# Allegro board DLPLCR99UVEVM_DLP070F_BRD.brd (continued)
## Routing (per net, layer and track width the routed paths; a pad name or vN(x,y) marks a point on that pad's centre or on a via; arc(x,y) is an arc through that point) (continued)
VDD_DMD: length 187.1
  TOP w0.381: C52.2 v1(107.32,20.75) ; C134.2 v1(47.4,51.69) ; R58.2 91.33,84.91 v1(92.19,84.05) ; C103.2 v1(64.25,61.73) ; C45.2 v1(102.87,15.04) ; C49.2 48.92,3.58 v1(49.65,3.58) ; C147.2 v1(96.18,9.43) ; C150.2 v1(46.13,26.29) ; C73.2 84.93,3.99 v1(84.7,3.76) ; U22.5 v1(111.3,22.06) ; C64.2 v1(43.59,26.92) ; C57.2 v1(104.14,16.94) ; v1(105.51,15.05) 105.79,15.33 U23.5 ; C66.2 v1(104.14,39.8) ; C102.2 v1(62.35,61.73) ; C81.2 55.27,4.85 v1(56,4.85) ; C93.2 50.14,6.89 v1(50.28,6.76) ; C146.2 v1(43.59,32.64) ; C130.2 v1(104.14,41.71) ; C78.2 v1(43.59,36.45) ; C84.2 v1(85.21,61.73) ; C56.2 v1(78.22,68.08) ; C60.2 v1(86.66,4.35) ; C154.2 51.46,6.12 v1(52.19,6.12) ; C95.2 53.37,5.49 v1(54.09,5.49) ; C100.2 v1(43.59,30.73) ; C109.2 v1(68.06,61.73) ; C112.2 v1(76.32,64.91) ; C54.2 v1(107.95,48.06) ; C166.2 v1(83.3,61.73) ; v1(82.57,83.51) 82.57,84.61 82.3,84.87 R61.2 81.44,84.87 81.17,84.6 v1(81.17,83.51) ; C126.2 v1(53.12,57.4) ; C196.2 v1(93.23,86.38) ; C61.2 v1(88.56,4.35) ; C156.2 96.66,6.51 v1(96.66,7.24) ; C53.2 v1(102.24,8.69) ; C105.2 v1(47.4,11.05) ; C79.2 v1(43.59,34.54) ; C51.2 v1(94.28,3.72) ; v1(42.79,9.02) 43.22,9.45 C72.2 ; C153.2 v1(58.54,61.73) ; C80.2 v1(43.59,38.35) ; C151.2 v1(100.33,11.23) ; C99.2 v1(46.13,14.86) ; C157.2 v1(46.13,16.76) ; C62.2 v1(94.28,7.53) ; C104.2 v1(48.67,9.14) ; C132.2 v1(46.13,49.78) ; C131.2 v1(41.05,44.07) ; C145.2 106.68,37.9 ; C55.2 v1(101.08,63.64) ; C83.2 v1(102.87,55.04) ; v1(54.88,57.58) 54.88,58.3 C127.2 ; v1(56.15,59.49) 56.29,59.63 C111.2 ; C85.2 v1(46.13,20.57) ; C164.2 v1(46.77,12.95) ; C110.2 v1(66.16,61.73) ; C152.2 v1(107.32,40.44) ; C40.2 v1(98.54,61.1) ; C101.2 v1(43.59,28.83) ; C47.2 v1(56.63,64.27) ; C67.2 v1(92.37,5.62) ; C107.2 v1(60.44,61.73) ; C129.2 v1(90.47,4.99) ; C133.2 v1(43.59,40.26) ; C43.2 v1(104.14,24.56) ; C171.2 v1(100.97,13.13) ; C167.2 v1(90.92,61.73) ; C48.2 v1(46.13,47.88) ; C42.2 v1(103.27,18.95) ; C65.2 v1(98.09,10.7) ; C59.2 v1(82.85,4.35) ; C200.2 v1(108.59,43.55) ; C50.2 v1(40.42,22.48)
  TOP w0.508: v1(109.21,25.4) 108.96,25.14 C74.2 ; C69.2 v1(65.65,64.64) ; C75.2 108.32,45.54 v1(108.58,45.29) ; v1(39.13,34.75) 39.41,34.47 C71.2 ; C91.1 v1(91.02,69.8) ; C91.1 93.87,68.22 94.25,67.84 v1(96.16,67.84) ; C91.1 93.87,70.26 94.5,70.89 v1(96.16,70.89) ; v1(83.96,66.12) 84.17,65.91 C76.2 ; C92.1 60.21,70.76 60.6,71.14 v1(62.5,71.14) ; C92.1 58.61,69.8 v1(57.8,69) ; C92.1 60.21,68.1 60.47,67.84 v1(62.5,67.84) ; v1(38.96,45.19) 39.16,45.39 C70.2
  BOTTOM w0.381: TP15.1 98.16,86.54 ; TP15.1 98.16,88.76 ; TP15.1 95.93,86.54 ; TP15.1 95.93,88.76
  BOTTOM w0.508: U16.AF18 v1(78.86,45.98) ; U16.T4 v1(58.54,33.28) ; U16.AF10 v1(66.16,45.98) ; U16.AF6 v1(61.08,45.98) ; U16.D20 v1(81.4,18.04) ; U16.D24 v1(86.48,18.04) ; U16.AJ1 v1(54.73,49.79) ; U16.H16 v1(73.78,23.12) ; U16.H28 v1(91.56,23.12) ; U16.F10 v1(66.16,20.58) ; U16.AE13 v1(69.97,44.71) ; U16.AF28 v1(91.56,45.98) ; U16.Y28 v1(91.56,38.36) ; U16.A3 v1(57.27,14.23) ; U16.AD12 v1(68.7,43.44) ; U16.H24 v1(86.48,23.12) ; U16.AH18 v1(78.86,48.52) ; U16.V28 v1(91.56,35.82) ; U16.D8 v1(63.62,18.04) ; U16.AF26 v1(89.02,45.98) ; U16.F8 v1(63.62,20.58) ; U16.AJ29 v1(92.83,49.79) ; U16.B4 v1(58.54,15.5) ; U16.AH14 v1(71.24,48.52) ; U16.C21 v1(82.67,16.77) ; U16.C29 v1(92.83,16.77) ; U16.AL29 v1(92.83,52.33) ; U16.N29 v1(92.83,29.47) ; U16.C1 v1(54.73,16.77) ; U16.AF12 v1(68.7,45.98) ; U16.AH12 v1(68.7,48.52) ; U16.H22 v1(83.94,23.12) ; U16.F16 v1(73.78,20.58) ; U16.T28 v1(91.56,33.28) ; U16.AA29 v1(92.83,39.63) ; U16.F18 v1(78.86,20.58) ; U16.A29 v1(92.83,14.23) ; U16.AJ21 v1(82.67,49.79) ; U16.AH10 v1(66.16,48.52) ; U16.AD28 v1(91.56,43.44) ; U16.AJ5 v1(59.81,49.79) ; U16.AF24 v1(86.48,45.98) ; U16.H20 v1(81.4,23.12) ; U16.H18 v1(78.86,23.12) ; U16.AD10 v1(66.16,43.44) ; U16.AJ31 v1(95.37,49.79) ; U16.AH16 v1(73.78,48.52) ; U16.AB4 v1(58.54,40.9) ; U16.AE15 v1(72.51,44.71) ; U16.P28 v1(91.56,30.74) ; U16.AK2 v1(56,51.06) ; U16.AF22 v1(83.94,45.98) ; U16.AJ11 v1(67.43,49.79) ; U16.F20 v1(81.4,20.58) ; U16.L3 v1(57.27,26.93) ; U16.V4 v1(58.54,35.82) ; U16.F12 v1(68.7,20.58) ; U16.D18 v1(78.86,18.04) ; U16.D16 v1(73.78,18.04) ; U16.C13 v1(69.97,16.77) ; U16.AD8 v1(63.62,43.44) ; U16.P4 v1(58.54,30.74) ; U16.D12 v1(68.7,18.04) ; U16.K4 v1(58.54,25.66) ; U16.C31 v1(95.37,16.77) ; U16.M4 v1(58.54,28.2)
VDDA_DMD: length 52.8
  TOP w0.381: 70.03,85.91 TP16.1 ; TP16.1 72.25,88.13 ; TP16.1 72.25,85.91 ; TP16.1 70.03,88.13 ; C98.2 v1(106.68,26.53) ; C148.2 v1(104.14,22.64) ; C97.2 v1(106.68,28.41)
  LY2-SIG w0.381: 70.03,85.91 TP16.1 ; TP16.1 70.03,88.13 ; TP16.1 72.25,88.13 ; TP16.1 72.25,85.91
  BOTTOM w0.381: v1(112.69,25.7) 110.89,27.51 C124.2 ; C115.2 v1(108.35,52.96) ; C113.2 v1(91.56,67.84) ; v1(73.3,70.08) 75.12,70.08 C123.2
  BOTTOM w0.508: U16.H26 v1(89.02,23.12) ; U16.D14 v1(71.24,18.04) ; U16.AE27 v1(90.29,44.71) ; U16.AH24 v1(86.48,48.52) ; U16.G11 v1(67.43,21.85) ; U16.K28 v1(91.56,25.66) ; U16.AD22 v1(83.94,43.44) ; U16.AB28 v1(91.56,40.9) ; U16.G15 v1(72.51,21.85) ; U16.AF20 v1(81.4,45.98) ; U16.AH20 v1(81.4,48.52) ; U16.AD18 v1(78.86,43.44) ; U16.H10 v1(66.16,23.12) ; U16.D10 v1(66.16,18.04) ; U16.F6 v1(61.08,20.58) ; U16.H12 v1(68.7,23.12) ; U16.AE19 v1(80.13,44.71) ; U16.H8 v1(63.62,23.12) ; U16.H14 v1(71.24,23.12) ; U16.AD16 v1(73.78,43.44) ; U16.AD24 v1(86.48,43.44) ; U16.AD14 v1(71.24,43.44)
  vias: v1(70.81,84.56) v1(71.92,85.01)
AMUX_OUT: length 79.8
  TOP w0.203: J8.1 v1(142.76,18.19)
  LY2-SIG w0.145: v1(77.59,19.31) 76.72,18.44 76.72,16.41 81.04,12.09 97.04,12.09 98.95,13.99 103.9,13.99 105.17,12.72 114.7,12.72 116.73,14.76 141.11,14.76 142.76,16.41 v1(142.76,18.19)
  BOTTOM w0.508: U16.E17 v1(77.59,19.31)
DCLK_AN: length 146
  TOP w0.127: v1(74.06,109.73) 74.44,110.11 74.44,110.63 74.11,110.97 74.11,112.77 73.48,113.4 73.48,115.2 73.36,115.32 J1.34
  LY4-SIG w0.127: v1(74.06,109.73) 74.31,109.48 74.31,108.23 78.1,104.44 78.1,78.21 77.43,77.55 74.97,77.55 74.18,78.33 74.18,92.79 72.2,94.77 68.85,94.77 67.07,92.99 67.07,73.49 62.78,69.19 59.08,69.19 47.51,57.63 47.51,52.98 49.8,50.7 49.8,42.52 53.26,39.06 53.26,32.18 54.73,30.7 v1(54.73,29.47)
  BOTTOM w0.508: U16.N1 v1(54.73,29.47)
DCLK_AP: length 145.6
  TOP w0.127: v1(74.98,109.73) 74.7,110.01 74.7,110.74 74.36,111.07 74.36,112.88 73.74,113.5 73.74,115.2 73.86,115.32 J1.33
  LY4-SIG w0.127: v1(74.98,109.73) 74.62,109.37 74.62,108.36 78.41,104.57 78.41,78.08 77.56,77.24 74.84,77.24 73.88,78.2 73.88,92.66 72.08,94.46 68.98,94.46 67.38,92.86 67.38,73.36 62.91,68.88 59.21,68.88 47.82,57.5 47.82,53.11 50.11,50.83 50.11,42.65 53.57,39.19 53.57,32.31 55.14,30.74 v1(56,30.74)
  BOTTOM w0.508: U16.P2 v1(56,30.74)
DCLK_BN: length 152.1
  TOP w0.127: J2.34 117.18,115.32 117.3,115.2 117.3,113.4 117.87,112.82 117.87,110.85 v1(117.54,110.51)
  LY4-SIG w0.127: v1(117.54,110.51) 117.85,110.21 117.85,108.94 121.45,105.33 121.45,96.27 119.95,94.77 119.95,93.67 121.42,92.2 121.42,41.93 121.13,41.63 120.07,41.63 119.78,41.93 119.78,45.77 119.16,46.38 118.11,46.38 117.57,45.85 117.57,35.61 105.99,24.03 104,24.03 101.25,21.27 101.25,18.73 92.78,10.26 83.21,10.26 81.1,12.37 81.1,14.88 80.59,15.39 80.1,15.39 79.8,15.09 79.28,15.09 v1(78.86,15.5)
  BOTTOM w0.508: U16.B18 v1(78.86,15.5)
DCLK_BP: length 151.8
  TOP w0.127: J2.33 117.68,115.17 117.55,115.05 117.55,113.5 118.13,112.93 118.13,110.85 v1(118.46,110.51)
  LY4-SIG w0.127: v1(80.13,14.23) 80.13,14.98 80.23,15.08 80.46,15.08 80.79,14.76 80.79,12.24 83.08,9.95 92.91,9.95 101.56,18.61 101.56,21.15 104.13,23.72 106.11,23.72 117.88,35.48 117.88,45.72 118.24,46.07 119.03,46.07 119.47,45.64 119.47,41.8 119.94,41.32 121.26,41.32 121.73,41.8 121.73,92.33 120.26,93.8 120.26,94.64 121.76,96.14 121.76,105.46 118.15,109.06 118.15,110.21 v1(118.46,110.51)
  BOTTOM w0.508: U16.A19 v1(80.13,14.23)
DCLK_CN: length 144.4
  LY6-SIG w0.107: v1(67.43,52.33) 68.18,53.07 68.36,53.07 68.86,52.56 68.86,52.37 68.18,51.69 67.1,51.69 63.55,55.24 63.55,92.18 63.84,92.48 64.49,92.48 64.79,92.18 64.79,61.31 65.36,60.73 66.54,60.73 67.07,61.26 67.07,94.12 72.79,99.84 72.79,103.24 78.78,109.24 80.05,109.24 80.53,109.72 80.53,111.4 v1(80.82,111.68)
  BOTTOM w0.127: v1(80.82,111.68) 80.48,112.02 80.48,113.49 81.24,114.24 81.24,115.2 81.36,115.32 J3.34
  BOTTOM w0.508: U16.AL11 v1(67.43,52.33)
DCLK_CP: length 144
  LY6-SIG w0.107: v1(69.97,52.33) 69.26,52.33 68.31,51.38 66.97,51.38 63.24,55.11 63.24,92.31 63.71,92.79 64.62,92.79 65.1,92.31 65.1,61.44 65.49,61.04 66.41,61.04 66.76,61.39 66.76,94.25 72.48,99.97 72.48,103.37 78.66,109.55 79.93,109.55 80.23,109.85 80.23,111.35 v1(79.9,111.68)
  BOTTOM w0.127: J3.33 80.86,115.32 80.98,115.2 80.98,114.34 80.23,113.59 80.23,112.02 v1(79.9,111.68)
  BOTTOM w0.508: U16.AL13 v1(69.97,52.33)
DCLK_DN: length 145.7
  LY6-SIG w0.107: v1(94.1,48.52) 94.55,48.52 94.89,48.18 94.89,47.85 94.59,47.56 94.02,47.56 93.39,48.18 93.39,48.82 94.89,50.31 105.63,50.31 107.45,52.14 109.57,52.14 121.61,64.18 121.61,79.65 122.07,80.11 122.75,80.11 122.95,79.91 122.95,67.64 123.51,67.08 124.68,67.08 125.22,67.62 125.22,104.9 125.57,105.25 126.2,105.25 126.43,105.02 126.43,95.63 126.89,95.17 127.43,95.17 127.99,95.73 127.99,106.25 127.43,106.81 125.21,106.81 124.51,107.51 124.51,111.08 124.33,111.26 124.33,111.38 v1(124.63,111.68)
  BOTTOM w0.127: J4.34 125.17,115.32 125.05,115.2 125.05,114.24 124.3,113.49 124.3,112.02 v1(124.63,111.68)
  BOTTOM w0.508: U16.AH30 v1(94.1,48.52)
DCLK_DP: length 145.3
  LY6-SIG w0.107: v1(123.71,111.68) 124.02,111.38 124.02,111.13 124.2,110.95 124.2,107.38 125.09,106.5 127.3,106.5 127.68,106.12 127.68,95.86 127.3,95.48 127.02,95.48 126.74,95.76 126.74,105.15 126.33,105.56 125.45,105.56 124.91,105.02 124.91,67.74 124.55,67.39 123.64,67.39 123.26,67.77 123.26,80.03 122.88,80.42 121.94,80.42 121.3,79.78 121.3,64.31 109.44,52.45 107.33,52.45 105.5,50.62 94.76,50.62 93.08,48.94 93.08,48.06 93.89,47.25 v1(95.37,47.25)
  BOTTOM w0.127: v1(123.71,111.68) 124.05,112.02 124.05,113.59 124.8,114.34 124.8,115.2 124.67,115.32 J4.33
  BOTTOM w0.508: U16.AG31 v1(95.37,47.25)
DD_A0N: length 153.3
  TOP w0.127: v1(81.11,113.33) 81.48,113.7 81.48,115.2 81.36,115.32 J1.18
  LY4-SIG w0.127: v1(81.11,113.33) 81.37,113.59 81.37,114.81 77.43,118.74 58.46,118.74 36.01,96.3 36.01,30.81 43.75,23.07 44.39,23.07 45.74,21.72 49.38,21.72 51.47,19.62 54.21,19.62 54.45,19.86 54.98,19.86 55.21,19.63 55.69,19.63 56,19.94 v1(56,20.58)
  BOTTOM w0.508: U16.F2 v1(56,20.58)
DD_A0P: length 152.6
  TOP w0.127: v1(82.03,113.33) 81.74,113.63 81.74,115.2 81.86,115.32 J1.17
  LY4-SIG w0.127: v1(82.03,113.33) 81.68,113.69 81.68,114.93 77.56,119.05 58.33,119.05 35.7,96.42 35.7,30.68 43.63,22.76 44.26,22.76 45.61,21.41 49.25,21.41 51.34,19.31 v1(54.73,19.31)
  BOTTOM w0.508: U16.E1 v1(54.73,19.31)
DD_A1N: length 148.9
  TOP w0.127: J1.22 79.36,115.32 79.48,115.2 79.48,114.23 80.13,113.58 80.13,113.06 79.14,112.07 79.14,110.92 v1(78.81,110.59)
  LY4-SIG w0.127: v1(78.81,110.59) 79.09,110.87 79.09,112.12 80.07,113.11 80.07,113.64 79.49,114.22 79.49,114.39 78.55,115.34 68.29,115.34 64.91,111.96 62.17,111.96 52.34,102.13 52.34,100.02 40.63,88.31 40.63,45.53 39.49,44.4 39.49,41.04 40.63,39.9 40.63,27.76 43.18,25.21 44.86,25.21 46.58,23.49 50.09,23.49 52.3,21.28 55.06,21.28 55.41,21.64 55.41,22.48 55.03,22.87 55.03,23.55 54.75,23.82 53.94,23.82 53.72,23.61 53.72,22.86 v1(54.73,21.85)
  BOTTOM w0.508: U16.G1 v1(54.73,21.85)
DD_A1P: length 148.4
  TOP w0.127: v1(79.72,110.59) 79.39,110.92 79.39,111.96 80.38,112.95 80.38,113.69 79.74,114.34 79.74,115.2 79.86,115.32 J1.21
  LY4-SIG w0.127: v1(79.72,110.59) 79.4,110.92 79.4,111.99 80.38,112.98 80.38,113.77 79.8,114.34 79.8,114.52 78.68,115.65 68.16,115.65 64.79,112.27 62.04,112.27 52.03,102.26 52.03,100.15 40.32,88.44 40.32,45.66 39.18,44.53 39.18,40.91 40.32,39.77 40.32,27.63 43.05,24.9 44.73,24.9 46.45,23.18 49.96,23.18 52.17,20.97 55.19,20.97 55.72,21.51 55.72,22.61 55.34,23 55.34,23.79 v1(54.73,24.39)
  BOTTOM w0.508: U16.J1 v1(54.73,24.39)
DD_A2N: length 154
  TOP w0.127: J1.26 77.36,115.32 77.48,115.2 77.48,113.26 78.15,112.59 78.15,112.04 77.28,111.18 77.28,110.66 v1(76.95,110.33)
  LY4-SIG w0.127: v1(76.95,110.33) 77.33,109.95 77.33,107.21 80.69,103.85 80.69,86.79 90.9,76.58 90.9,72.85 88.59,70.54 74.7,70.54 73.29,69.13 73.29,63.6 68.34,58.65 58.41,58.65 51.6,51.84 51.6,43.2 53.42,41.38 54.11,41.38 57.85,37.64 57.85,36.6 57.34,36.09 57.34,35.35 57.87,34.82 57.87,34.24 57.47,33.84 57.47,32.78 58,32.26 58,31.65 57.44,31.09 57.44,30.43 57.9,29.97 57.9,29.13 57.4,28.63 57.4,27.81 57.95,27.25 57.95,26.7 57.4,26.14 57.4,25.34 57.92,24.81 57.92,24.13 57.57,23.78 57.57,22.6 64.28,15.9 64.28,14.88 62.88,13.49 62.05,13.49 60.99,14.54 60.46,14.54 60.27,14.73 60.27,15.26 60.5,15.5 v1(61.08,15.5)
  BOTTOM w0.508: U16.B6 v1(61.08,15.5)
DD_A2P: length 153.4
  TOP w0.127: J1.25 77.86,115.32 77.74,115.2 77.74,113.36 78.4,112.7 78.4,111.94 77.54,111.07 77.54,110.66 v1(77.87,110.33)
  LY4-SIG w0.127: v1(77.87,110.33) 77.64,110.1 77.64,107.34 81,103.98 81,86.92 91.21,76.71 91.21,72.72 88.71,70.23 74.83,70.23 73.6,69 73.6,63.47 68.47,58.34 58.54,58.34 51.91,51.71 51.91,43.32 53.55,41.69 54.24,41.69 58.16,37.77 58.16,36.47 57.65,35.97 57.65,35.48 58.18,34.95 58.18,34.11 57.78,33.71 57.78,32.91 58.31,32.38 58.31,31.52 57.75,30.96 57.75,30.56 58.21,30.1 58.21,29.01 57.71,28.5 57.71,27.93 58.26,27.38 58.26,26.57 57.71,26.01 57.71,25.47 58.23,24.94 58.23,24 57.88,23.65 57.88,22.73 64.59,16.03 64.59,14.75 63.01,13.18 61.92,13.18 60.87,14.23 v1(59.81,14.23)
  BOTTOM w0.508: U16.A5 v1(59.81,14.23)
DD_A3N: length 151.9
  TOP w0.127: v1(75.38,111.25) 75.71,111.58 75.71,112.6 76.17,113.06 76.17,113.69 75.48,114.37 75.48,115.2 75.36,115.32 J1.30
  LY4-SIG w0.127: v1(54.73,26.93) 54.73,26.43 54.91,26.26 55.24,26.26 55.69,26.72 55.69,26.97 54.96,27.71 48.89,27.71 45.71,30.88 45.71,35.66 47.89,37.85 47.89,41.35 44.08,45.16 44.08,58.67 49.32,63.91 49.32,72.5 55.36,78.54 55.36,88.24 56.68,89.56 58.21,89.56 59.05,88.72 59.05,73.74 59.53,73.26 60.98,73.26 61.48,73.77 61.48,93.12 73.21,104.84 73.21,110.15 73.7,110.64 75.49,110.64 75.68,110.83 75.68,110.95 v1(75.38,111.25)
  BOTTOM w0.508: U16.L1 v1(54.73,26.93)
DD_A3P: length 151.3
  TOP w0.127: J1.29 75.86,115.32 75.74,115.2 75.74,114.47 76.42,113.79 76.42,112.95 75.96,112.5 75.96,111.58 v1(76.3,111.25)
  LY4-SIG w0.127: v1(56,25.66) 56,27.09 55.08,28.02 49.01,28.02 46.02,31.01 46.02,35.53 48.2,37.72 48.2,41.48 44.39,45.29 44.39,58.54 49.63,63.78 49.63,72.37 55.67,78.41 55.67,88.11 56.81,89.25 58.08,89.25 58.74,88.59 58.74,73.61 59.4,72.95 61.11,72.95 61.79,73.64 61.79,92.99 73.52,104.72 73.52,110.03 73.83,110.33 75.62,110.33 75.99,110.7 75.99,110.95 v1(76.3,111.25)
  BOTTOM w0.508: U16.K2 v1(56,25.66)
DD_A4N: length 155
  TOP w0.127: J1.38 71.36,115.32 71.48,115.2 71.48,114.24 70.58,113.34 70.58,112.62 70.93,112.26 70.93,111 v1(70.62,110.69)
  LY4-SIG w0.127: v1(62.35,14.23) 62.78,14.65 62.78,14.85 56.45,21.18 56.45,22.5 56.55,22.61 56.55,23.64 55.21,24.99 49.09,24.99 44.09,29.99 44.09,30.94 43.8,31.23 42.82,31.23 41.83,32.22 41.83,63.04 47.06,68.27 47.06,90.42 47.85,91.21 49.22,91.21 49.9,90.52 49.9,80.12 50.88,79.15 52.33,79.15 53.46,80.27 53.46,89.1 70.91,106.55 70.91,110.41 v1(70.62,110.69)
  BOTTOM w0.508: U16.A7 v1(62.35,14.23)
DD_A4P: length 154.4
  TOP w0.127: J1.37 71.86,115.32 71.74,115.2 71.74,114.14 70.83,113.23 70.83,112.72 71.19,112.37 71.19,111.05 v1(71.54,110.69)
  LY4-SIG w0.127: v1(71.54,110.69) 71.22,110.36 71.22,106.42 53.77,88.98 53.77,80.14 52.46,78.84 50.75,78.84 49.59,79.99 49.59,90.4 49.09,90.9 47.97,90.9 47.37,90.29 47.37,68.15 42.14,62.91 42.14,32.35 42.95,31.54 43.92,31.54 44.4,31.07 44.4,30.12 49.22,25.3 55.34,25.3 56.86,23.77 56.86,22.48 56.76,22.38 56.76,21.31 62.57,15.5 v1(63.62,15.5)
  BOTTOM w0.508: U16.B8 v1(63.62,15.5)
DD_A5N: length 152.6
  TOP w0.127: v1(68.54,111.93) 68.88,112.26 68.88,113.13 69.92,114.18 69.92,114.53 69.48,114.96 69.48,115.2 69.36,115.32 J1.42
  LY6-SIG w0.107: v1(68.54,111.93) 68.85,112.23 68.85,112.97 68.5,113.33 68.5,114.93 67.21,116.22 62.45,116.22 40.96,94.74 40.96,45.45 41.98,44.43 41.98,19.89 44.23,17.63 47.11,17.63 51.33,13.41 66.18,13.41 66.87,14.1 66.87,14.65 66.64,14.88 65.55,14.88 v1(64.89,14.23)
  BOTTOM w0.508: U16.A9 v1(64.89,14.23)
DD_A5P: length 152
  TOP w0.127: v1(69.46,111.93) 69.13,112.26 69.13,113.03 70.17,114.07 70.17,114.63 69.74,115.07 69.74,115.2 69.86,115.32 J1.41
  LY6-SIG w0.107: v1(67.43,14.23) 66.31,13.1 51.2,13.1 46.98,17.32 44.1,17.32 41.67,19.76 41.67,44.3 40.65,45.32 40.65,94.87 62.32,116.53 67.33,116.53 68.81,115.06 68.81,113.46 69.16,113.1 69.16,112.23 v1(69.46,111.93)
  BOTTOM w0.508: U16.A11 v1(67.43,14.23)
DD_A6N: length 144.2
  TOP w0.127: J1.46 67.36,115.32 67.49,115.2 67.49,115.02 66.16,113.69 66.16,109.98 v1(65.83,109.65)
  LY6-SIG w0.107: v1(56,33.28) 56.31,32.97 56.31,32.75 56.18,32.61 54.7,32.61 54.57,32.61 49.93,37.25 49.93,45.31 49.26,45.98 47.49,45.98 47.11,46.36 47.11,50.21 45.81,51.51 45.81,59.61 45.41,60.02 44.24,60.02 43.65,59.43 43.65,46.61 43.33,46.28 42.72,46.28 42.41,46.58 42.41,94.26 46.6,98.44 49.69,98.44 52.37,101.12 52.37,104.09 61.96,113.68 64.82,113.68 66.13,112.37 66.13,109.95 v1(65.83,109.65)
  BOTTOM w0.508: U16.T2 v1(56,33.28)
DD_A6P: length 143.5
  TOP w0.127: v1(66.75,109.65) 66.41,109.98 66.41,113.59 67.74,114.91 67.74,115.2 67.86,115.32 J1.45
  LY6-SIG w0.107: v1(54.73,32.01) 49.62,37.12 49.62,45.18 49.13,45.67 47.36,45.67 46.8,46.23 46.8,50.09 45.5,51.38 45.5,59.48 45.28,59.71 44.37,59.71 43.96,59.31 43.96,46.48 43.46,45.97 42.59,45.97 42.1,46.46 42.1,94.39 46.47,98.75 49.57,98.75 52.06,101.24 52.06,104.22 61.83,113.99 64.95,113.99 66.44,112.5 66.44,109.96 v1(66.75,109.65)
  BOTTOM w0.508: U16.R1 v1(54.73,32.01)
DD_A7N: length 138.8
  TOP w0.127: v1(62.07,112.95) 62.45,113.33 62.45,113.77 63.31,114.63 65.06,114.63 65.49,115.05 65.49,115.2 65.36,115.32 J1.50
  LY6-SIG w0.107: v1(54.73,34.55) 54.73,35.5 54.57,35.66 53.12,35.66 51.42,37.37 51.42,45.39 48.45,48.35 48.45,52.04 47.13,53.36 47.13,59.92 43.73,63.32 43.73,69.39 46.54,72.21 46.54,76.4 47.23,77.09 47.23,92.1 46.9,92.42 46.12,92.42 45.84,92.15 45.84,77.29 45.28,76.73 44.49,76.73 43.93,77.29 43.93,94.77 46.2,97.03 54.78,97.03 57.26,99.51 57.26,106.65 62.37,111.76 62.37,112.65 v1(62.07,112.95)
  BOTTOM w0.508: U16.U1 v1(54.73,34.55)
DD_A7P: length 138.1
  TOP w0.127: J1.49 65.86,115.32 65.74,115.2 65.74,114.95 65.17,114.38 63.42,114.38 62.7,113.66 62.7,113.24 v1(62.99,112.95)
  LY6-SIG w0.107: v1(62.99,112.95) 62.68,112.65 62.68,111.63 57.57,106.52 57.57,99.38 54.91,96.72 46.33,96.72 44.24,94.64 44.24,77.42 44.62,77.04 45.16,77.04 45.53,77.42 45.53,92.28 45.99,92.73 47.03,92.73 47.54,92.23 47.54,76.96 46.85,76.28 46.85,72.08 44.04,69.26 44.04,63.45 47.44,60.05 47.44,53.49 48.76,52.17 48.76,48.48 51.73,45.52 51.73,37.5 53.25,35.97 54.43,35.97 54.73,36.28 v1(54.73,37.09)
  BOTTOM w0.508: U16.W1 v1(54.73,37.09)
DD_B0N: length 158.2
  TOP w0.127: J2.18 125.17,115.32 125.42,115.08 125.42,113.82 v1(124.93,113.33)
  LY4-SIG w0.127: v1(124.93,113.33) 125.54,112.72 125.54,111.86 124.88,111.2 124.88,34.56 110.93,20.62 110.93,18.03 102.56,9.66 101.92,9.66 98.38,6.12 93.75,6.12 93.29,6.58 81.18,6.58 76.83,10.93 72.97,10.93 70.78,13.11 70.78,14.71 70.22,15.26 69.74,15.26 69.51,15.03 69.17,15.03 v1(68.7,15.5)
  BOTTOM w0.508: U16.B12 v1(68.7,15.5)
DD_B0P: length 157.8
  TOP w0.127: v1(125.85,113.33) 125.85,113.77 125.67,113.94 J2.17
  LY4-SIG w0.127: v1(69.97,14.23) 69.62,14.58 69.62,14.71 69.87,14.95 70.09,14.95 70.47,14.58 70.47,12.98 72.84,10.62 76.7,10.62 81.05,6.27 93.16,6.27 93.62,5.81 98.51,5.81 102.05,9.35 102.68,9.35 111.24,17.91 111.24,20.49 125.19,34.43 125.19,111.07 125.85,111.73 v1(125.85,113.33)
  BOTTOM w0.508: U16.A13 v1(69.97,14.23)
DD_B1N: length 126.6
  TOP w0.127: v1(122.62,110.59) 122.95,110.92 122.95,112.07 123.94,113.06 123.94,113.58 123.3,114.23 123.3,115.2 123.17,115.32 J2.22
  LY4-SIG w0.127: v1(95.37,32.01) 95.88,31.51 95.88,31.27 95.62,31.01 94.94,31.01 94.71,31.24 94.71,32.58 102.66,40.53 105.57,40.53 107.28,42.24 107.28,65.91 107.87,66.5 107.87,85.3 104.4,88.77 104.4,93.97 103.27,95.1 103.27,113.03 107.23,116.99 119.22,116.99 121.12,115.09 121.12,113.5 122.78,111.85 122.78,111.16 122.93,111.01 122.93,110.9 v1(122.62,110.59)
  BOTTOM w0.508: U16.R31 v1(95.37,32.01)
DD_B1P: length 125.9
  TOP w0.127: v1(123.54,110.59) 123.21,110.92 123.21,111.96 124.2,112.95 124.2,113.69 123.55,114.34 123.55,115.2 123.67,115.32 J2.21
  LY4-SIG w0.127: v1(123.54,110.59) 123.23,110.9 123.23,111.14 123.09,111.29 123.09,111.98 121.43,113.63 121.43,115.21 119.35,117.3 107.1,117.3 102.96,113.16 102.96,94.97 104.09,93.84 104.09,88.64 107.56,85.17 107.56,66.62 106.97,66.04 106.97,42.37 105.45,40.84 102.53,40.84 94.4,32.71 94.4,31.04 v1(94.1,30.74)
  BOTTOM w0.508: U16.P30 v1(94.1,30.74)
DD_B2N: length 156.6
  TOP w0.127: J2.26 121.17,115.32 121.3,115.2 121.3,113.26 121.96,112.59 121.96,112.04 121.51,111.58 121.51,110.72 121.38,110.6 121.23,110.6 v1(120.84,110.21)
  LY4-SIG w0.127: v1(72.51,14.23) 72.51,14.91 72.42,15.01 71.92,15.01 71.78,14.86 71.78,14.15 73.75,12.17 77.36,12.17 81.99,7.54 93.03,7.54 103.35,17.86 108.17,17.86 109.74,19.43 109.74,21.84 121.3,33.4 121.3,35.44 121.7,35.84 122.42,35.84 122.83,35.44 122.83,35.07 123.07,34.83 123.49,34.83 123.74,35.07 123.74,107.03 121.45,109.32 121.45,109.8 121.32,109.93 121.12,109.93 v1(120.84,110.21)
  BOTTOM w0.508: U16.A15 v1(72.51,14.23)
DD_B2P: length 156.1
  TOP w0.127: v1(121.76,110.21) 121.76,111.48 122.22,111.94 122.22,112.7 121.55,113.36 121.55,115.2 121.67,115.32 J2.25
  LY4-SIG w0.127: v1(121.76,110.21) 121.76,109.45 124.05,107.16 124.05,34.94 123.62,34.52 122.94,34.52 122.52,34.94 122.52,35.31 122.3,35.53 121.83,35.53 121.61,35.31 121.61,33.27 110.05,21.72 110.05,19.3 108.3,17.55 103.48,17.55 93.16,7.23 81.86,7.23 77.23,11.86 73.63,11.86 71.47,14.02 71.47,14.86 71.24,15.08 v1(71.24,15.5)
  BOTTOM w0.508: U16.B14 v1(71.24,15.5)
DD_B3N: length 155.1
  TOP w0.127: J2.30 119.18,115.32 119.3,115.2 119.3,114.37 119.98,113.69 119.98,113.03 119.57,112.63 119.57,111.97 v1(119.19,111.58)
  LY4-SIG w0.127: v1(119.19,111.58) 119.5,111.27 119.5,109.75 122.62,106.63 122.62,37.3 122.4,37.09 121.67,37.09 121.45,37.3 121.45,39.78 121.01,40.23 119.72,40.23 119.27,39.78 119.27,33.58 108.18,22.49 105.87,22.49 105.27,21.9 104.85,21.9 102.41,19.46 102.41,18.47 93.13,9.19 82.47,9.19 79.22,12.45 79.22,14 77.47,15.75 76.61,15.75 76.16,15.42 76.04,15.06 75.1,15.06 v1(73.78,15.5)
  BOTTOM w0.508: U16.B16 v1(73.78,15.5)
DD_B3P: length 154.4
  TOP w0.127: v1(120.11,111.58) 119.83,111.86 119.83,112.52 120.24,112.93 120.24,113.79 119.55,114.47 119.55,115.2 119.68,115.32 J2.29
  LY4-SIG w0.127: v1(77.59,14.23) 76.48,14.6 76.34,14.78 76.33,14.92 76.44,15.24 76.71,15.44 77.34,15.44 78.91,13.87 78.91,12.32 82.34,8.88 93.26,8.88 102.72,18.34 102.72,19.33 104.98,21.59 105.4,21.59 105.99,22.18 108.31,22.18 119.58,33.45 119.58,39.66 119.85,39.92 120.88,39.92 121.14,39.66 121.14,37.18 121.54,36.78 122.53,36.78 122.93,37.18 122.93,106.76 119.81,109.88 119.81,111.28 v1(120.11,111.58)
  BOTTOM w0.508: U16.A17 v1(77.59,14.23)
DD_B4N: length 150.5
  TOP w0.127: v1(114.42,110.41) 114.8,110.8 114.8,112.21 114.39,112.62 114.39,113.34 115.3,114.24 115.3,115.2 115.18,115.32 J2.38
  LY4-SIG w0.127: v1(82.67,14.23) 82.67,15.33 82.52,15.49 82.15,15.49 82.01,15.35 82.01,13.69 84.45,11.25 92.4,11.25 100.33,19.19 100.33,22.26 105.76,27.68 107.84,27.68 116.22,36.06 116.22,52.98 116.88,53.64 118,53.64 118.71,52.93 118.71,48.36 119.04,48.04 119.7,48.04 120.18,48.51 120.18,90.37 118.58,91.97 118.58,95.94 120.03,97.38 120.03,103.22 114.67,108.58 114.67,110.16 v1(114.42,110.41)
  BOTTOM w0.508: U16.A21 v1(82.67,14.23)
DD_B4P: length 149.9
  TOP w0.127: v1(115.34,110.41) 115.05,110.69 115.05,112.32 114.65,112.72 114.65,113.23 115.55,114.14 115.55,115.2 115.68,115.32 J2.37
  LY4-SIG w0.127: v1(115.34,110.41) 114.98,110.06 114.98,108.71 120.34,103.35 120.34,97.26 118.89,95.81 118.89,92.1 120.49,90.5 120.49,48.39 119.83,47.73 118.91,47.73 118.4,48.23 118.4,52.8 117.87,53.33 117.01,53.33 116.53,52.85 116.53,35.93 107.97,27.37 105.89,27.37 100.64,22.13 100.64,19.06 92.53,10.94 84.32,10.94 81.7,13.56 81.7,15.2 v1(81.4,15.5)
  BOTTOM w0.508: U16.B20 v1(81.4,15.5)
DD_B5N: length 132.3
  TOP w0.127: J2.42 113.18,115.32 113.3,115.2 113.3,114.96 113.73,114.53 113.73,114.18 112.59,113.03 112.59,111.71 v1(112.25,111.38)
  LY4-SIG w0.127: v1(95.37,26.93) 95.37,27.97 96.13,28.73 102.24,28.73 104.08,30.57 104.08,31.37 105.76,33.04 108.6,33.04 111.98,36.42 111.98,76.95 112.37,77.34 113.28,77.34 113.58,77.03 113.58,68.48 114.04,68.02 115.38,68.02 115.87,68.5 115.87,84.81 113.33,87.35 113.33,98.27 111.9,99.69 111.9,103.43 108.46,106.87 108.46,109.82 110.71,112.06 112.35,112.06 112.56,111.86 112.56,111.68 v1(112.25,111.38)
  BOTTOM w0.508: U16.L31 v1(95.37,26.93)
DD_B5P: length 131.7
  TOP w0.127: v1(113.17,111.38) 112.84,111.71 112.84,112.93 113.99,114.07 113.99,114.63 113.55,115.07 113.55,115.2 113.68,115.32 J2.41
  LY4-SIG w0.127: v1(95.37,29.47) 95.84,29.01 102.08,29.01 103.77,30.69 103.77,31.5 105.63,33.35 108.47,33.35 111.67,36.55 111.67,77.08 112.24,77.65 113.4,77.65 113.89,77.16 113.89,68.61 114.17,68.33 115.26,68.33 115.56,68.63 115.56,84.68 113.02,87.22 113.02,98.14 111.59,99.57 111.59,103.3 108.15,106.74 108.15,109.94 110.58,112.37 112.48,112.37 112.87,111.99 112.87,111.68 v1(113.17,111.38)
  BOTTOM w0.508: U16.N31 v1(95.37,29.47)
DD_B6N: length 135.8
  TOP w0.127: v1(109.64,109.65) 109.97,109.98 109.97,113.69 111.3,115.02 111.3,115.2 111.18,115.32 J2.46
  LY4-SIG w0.127: v1(109.64,109.65) 109.95,109.35 109.95,107.93 115.61,102.26 115.61,87.83 117.13,86.31 117.13,58.29 116.73,57.89 115.79,57.89 115.38,58.29 115.38,65.99 114.75,66.63 113.61,66.63 113.02,66.04 113.02,36.2 108.24,31.42 105.83,31.42 105.07,30.66 105.07,29.64 98.28,22.86 98.28,20.6 97.42,19.74 97.07,19.74 96.77,20.04 96.77,22.22 96.3,22.69 95.87,22.69 95.37,23.18 v1(95.37,24.39)
  BOTTOM w0.508: U16.J31 v1(95.37,24.39)
DD_B6P: length 135.1
  TOP w0.127: v1(110.56,109.65) 110.23,109.98 110.23,113.59 111.55,114.91 111.55,115.2 111.68,115.32 J2.45
  LY4-SIG w0.127: v1(110.56,109.65) 110.26,109.35 110.26,108.05 115.92,102.39 115.92,87.96 117.44,86.44 117.44,58.16 116.86,57.58 115.66,57.58 115.07,58.16 115.07,65.86 114.62,66.32 113.73,66.32 113.33,65.91 113.33,36.07 108.37,31.11 105.96,31.11 105.38,30.53 105.38,29.51 98.59,22.73 98.59,20.47 97.55,19.43 96.94,19.43 96.46,19.91 96.46,22.09 96.17,22.38 95.9,22.38 v1(95.37,21.85)
  BOTTOM w0.508: U16.G31 v1(95.37,21.85)
DD_B7N: length 148
  TOP w0.127: J2.50 109.18,115.32 109.3,115.2 109.3,115.05 108.88,114.63 107,114.63 106.16,113.79 106.16,113.34 v1(105.85,113.03)
  LY4-SIG w0.127: v1(105.85,113.03) 106.16,112.72 106.16,112.09 106.49,111.76 107.16,111.76 108.66,113.26 108.66,114.13 110.05,115.52 113.1,115.52 113.78,114.83 113.78,114.02 114.32,113.49 114.32,112.6 114.69,112.22 114.69,111.66 114.41,111.38 113.94,111.38 113.11,110.55 113.11,108.41 117.51,104.01 117.51,88.21 118.53,87.2 118.53,57.68 114.9,54.04 114.9,36.22 108.27,29.59 106.37,29.59 99.28,22.5 99.28,19.66 91.96,12.34 85.6,12.34 84.25,13.68 84.25,15.1 84.55,15.39 84.75,15.39 84.93,15.21 84.93,14.51 v1(85.21,14.23)
  BOTTOM w0.508: U16.A23 v1(85.21,14.23)
DD_B7P: length 147.5
  TOP w0.127: v1(106.77,113.03) 106.42,113.38 106.42,113.69 107.1,114.38 108.98,114.38 109.55,114.95 109.55,115.2 109.68,115.32 J2.49
  LY4-SIG w0.127: v1(106.77,113.03) 106.47,112.73 106.47,112.22 106.62,112.07 107.03,112.07 108.35,113.38 108.35,114.25 109.92,115.83 113.23,115.83 114.09,114.96 114.09,114.15 114.63,113.61 114.63,112.73 115,112.35 115,111.53 114.54,111.07 114.06,111.07 113.42,110.42 113.42,108.54 117.82,104.14 117.82,88.34 118.84,87.32 118.84,57.55 115.21,53.92 115.21,36.09 108.4,29.29 106.5,29.29 99.59,22.37 99.59,19.54 92.09,12.03 85.47,12.03 83.94,13.56 v1(83.94,15.5)
  BOTTOM w0.508: U16.B22 v1(83.94,15.5)
DD_C0N: length 138.6
  LY6-SIG w0.107: v1(73.55,112.55) 73.25,112.25 73.25,109.82 73.73,109.35 73.73,108.76 62.71,97.74 62.71,96.75 59.66,93.7 59.66,80.44 59.2,79.98 58.28,79.98 57.87,80.39 57.87,89.99 57.57,90.3 56.25,90.3 55.85,89.89 55.85,60.75 55.35,60.25 54,60.25 53.5,60.75 53.5,75.7 53.24,75.97 52.46,75.97 52.19,75.7 52.19,59.44 52.85,58.78 55.11,58.78 55.85,58.04 55.85,55.3 59.61,51.54 60.34,51.54 61.32,52.52 61.32,52.64 60.84,53.12 60.61,53.12 v1(59.81,52.33)
  BOTTOM w0.127: v1(73.55,112.55) 73.24,112.86 73.24,115.2 73.36,115.32 J3.18
  BOTTOM w0.508: U16.AL5 v1(59.81,52.33)
DD_C0P: length 138.1
  LY6-SIG w0.107: v1(72.63,112.55) 72.94,112.24 72.94,109.69 73.42,109.22 73.42,108.89 62.4,97.87 62.4,96.88 59.35,93.83 59.35,80.57 59.07,80.29 58.41,80.29 58.18,80.52 58.18,90.12 57.7,90.61 56.12,90.61 55.54,90.02 55.54,60.87 55.22,60.56 54.13,60.56 53.81,60.87 53.81,75.83 53.37,76.28 52.33,76.28 51.88,75.83 51.88,59.31 52.72,58.47 54.98,58.47 55.54,57.91 55.54,55.17 59.48,51.23 60.47,51.23 61.56,52.33 v1(62.35,52.33)
  BOTTOM w0.127: v1(72.63,112.55) 72.98,112.9 72.98,115.2 72.86,115.32 J3.17
  BOTTOM w0.508: U16.AL7 v1(62.35,52.33)
DD_C1N: length 130.8
  LY6-SIG w0.107: v1(56,45.98) 55.54,46.44 55.54,46.57 58.28,49.3 58.87,49.3 59.22,48.94 60.49,48.94 63.77,52.22 63.77,53.02 57.6,59.18 57.6,67.89 57.22,68.28 57.22,78.03 57.66,78.46 58.86,78.46 59.35,77.98 59.35,58.68 59.91,58.11 61,58.11 61.59,58.7 61.59,92.97 69.23,100.61 69.77,100.61 71.9,102.74 71.9,104.47 76.04,108.61 76.04,109.83 74.77,111.09 74.77,111.76 75.27,112.25 75.27,113 v1(75.57,113.31)
  BOTTOM w0.127: J3.22 75.36,115.32 75.24,115.2 75.24,113.64 v1(75.57,113.31)
  BOTTOM w0.508: U16.AF2 v1(56,45.98)
DD_C1P: length 130.2
  LY6-SIG w0.107: v1(54.73,47.25) 55.79,47.25 58.15,49.61 59,49.61 59.35,49.25 60.37,49.25 63.46,52.35 63.46,52.89 57.29,59.05 57.29,67.77 56.91,68.15 56.91,78.15 57.53,78.77 58.99,78.77 59.66,78.1 59.66,58.8 60.04,58.42 60.88,58.42 61.28,58.83 61.28,93.1 69.1,100.92 69.64,100.92 71.59,102.87 71.59,104.6 75.73,108.74 75.73,109.7 74.46,110.96 74.46,111.89 74.96,112.38 74.96,113 v1(74.65,113.31)
  BOTTOM w0.127: v1(74.65,113.31) 74.98,113.64 74.98,115.2 74.86,115.32 J3.21
  BOTTOM w0.508: U16.AG1 v1(54.73,47.25)
DD_C2N: length 127.1
  LY6-SIG w0.107: v1(54.73,44.71) 54.73,43.83 54.82,43.74 55.07,43.74 55.54,44.2 55.54,44.75 52.56,47.72 52.56,55.35 50.51,57.4 50.51,87.07 51.15,87.71 52.19,87.71 52.72,87.17 52.72,78.01 53.13,77.6 53.76,77.6 54.09,77.93 54.09,90.14 61.03,97.08 61.03,99.08 70.78,108.83 70.78,109.37 71.44,110.03 71.69,110.03 72.05,110.39 72.05,110.97 71.72,111.3 71.72,113.08 73.45,114.81 73.45,119.38 74.11,120.04 76.42,120.04 77.33,119.12 77.33,112.62 v1(77.64,112.32)
  BOTTOM w0.127: v1(77.64,112.32) 77.24,112.72 77.24,115.2 77.36,115.32 J3.26
  BOTTOM w0.508: U16.AE1 v1(54.73,44.71)
DD_C2P: length 126.6
  LY6-SIG w0.107: v1(54.73,42.17) 54.73,42.96 55.85,44.07 55.85,44.88 52.87,47.85 52.87,55.48 50.82,57.53 50.82,86.94 51.28,87.4 52.06,87.4 52.41,87.04 52.41,77.88 53,77.29 53.89,77.29 54.4,77.8 54.4,90.02 61.34,96.95 61.34,98.96 71.09,108.7 71.09,109.24 71.57,109.72 71.82,109.72 72.36,110.26 72.36,111.1 72.03,111.43 72.03,112.95 73.76,114.68 73.76,119.25 74.24,119.73 76.29,119.73 77.02,119 77.02,112.62 v1(76.72,112.32)
  BOTTOM w0.127: v1(76.72,112.32) 76.72,112.77 76.98,113.03 76.98,115.2 76.86,115.32 J3.25
  BOTTOM w0.508: U16.AC1 v1(54.73,42.17)
DD_C3N: length 130.1
  LY6-SIG w0.107: v1(56,40.9) 56,39.48 55.13,38.61 53.71,38.61 53.02,39.3 53.02,45.39 50.84,47.57 50.84,53.13 48.86,55.12 48.86,93.14 49.29,93.57 50.16,93.57 50.7,93.03 50.7,89.26 50.89,89.06 51.5,89.06 51.75,89.31 51.75,92.81 52.52,93.57 55.29,93.57 58.76,97.05 58.76,100.17 69.99,111.4 69.99,120.69 70.61,121.31 78.56,121.31 79.26,120.6 79.26,113.61 v1(79.57,113.31)
  BOTTOM w0.127: v1(79.57,113.31) 79.24,113.64 79.24,115.2 79.36,115.32 J3.30
  BOTTOM w0.508: U16.AB2 v1(56,40.9)
DD_C3P: length 129.5
  LY6-SIG w0.107: v1(78.65,113.31) 78.95,113.61 78.95,120.48 78.43,121 70.74,121 70.3,120.57 70.3,111.27 59.07,100.04 59.07,96.92 55.42,93.26 52.65,93.26 52.06,92.68 52.06,89.18 51.63,88.75 50.77,88.75 50.39,89.13 50.39,92.91 50.03,93.26 49.42,93.26 49.17,93.01 49.17,55.24 51.15,53.26 51.15,47.7 53.33,45.52 53.33,39.43 53.84,38.92 55.01,38.92 55.7,39.61 55.7,40.36 55.44,40.61 54.85,40.61 54.73,40.5 v1(54.73,39.63)
  BOTTOM w0.127: J3.29 78.86,115.32 78.98,115.2 78.98,113.64 v1(78.65,113.31)
  BOTTOM w0.508: U16.AA1 v1(54.73,39.63)
DD_C4N: length 139.5
  LY6-SIG w0.119: v1(64.89,52.33) 64.89,50.77 66.72,48.94 68.11,48.94 71.02,51.85 71.02,53.4 69.55,54.87 69.55,94.35 70.32,95.12 71.93,95.12 72.72,94.33 72.72,84.49 71.16,82.93 71.16,68.66 71.82,68 73.81,68 74.58,68.77 74.58,96.97 77.38,99.76 77.38,104.06 83.28,109.96 83.28,111.68 v1(83.58,111.99)
  BOTTOM w0.127: J3.38 83.36,115.32 83.24,115.2 83.24,112.33 v1(83.58,111.99)
  BOTTOM w0.508: U16.AL9 v1(64.89,52.33)
DD_C4P: length 138.9
  LY6-SIG w0.119: v1(82.66,111.99) 82.96,111.7 82.96,110.09 77.06,104.19 77.06,99.9 74.26,97.1 74.26,68.91 73.68,68.32 71.95,68.32 71.48,68.79 71.48,82.8 73.04,84.35 73.04,94.46 72.06,95.44 70.19,95.44 69.23,94.49 69.23,54.74 70.7,53.27 70.7,51.99 67.98,49.27 66.85,49.27 65.22,50.9 65.22,51.51 65.35,51.64 65.65,51.64 66.16,51.12 v1(66.16,51.06)
  BOTTOM w0.127: J3.37 82.86,115.32 82.98,115.2 82.98,112.31 v1(82.66,111.99)
  BOTTOM w0.508: U16.AK10 v1(66.16,51.06)
DD_C5N: length 145.8
  LY6-SIG w0.107: v1(84.93,110.9) 84.6,110.57 84.6,109.42 81.96,106.77 81.96,97.87 81.42,97.33 80.56,97.33 80.13,97.76 80.13,103.71 79.78,104.06 79.24,104.06 78.91,103.73 78.91,70.23 78.43,69.75 77.64,69.75 77.08,70.31 77.08,95.76 76.79,96.05 76.31,96.05 75.97,95.7 75.97,68.02 77.44,66.55 77.44,64.46 76.5,63.52 72.94,63.52 71.83,62.41 71.83,56.25 73.73,54.35 73.73,52.22 72.57,51.06 v1(71.24,51.06)
  BOTTOM w0.127: J3.42 85.36,115.32 85.23,115.2 85.23,113.64 84.57,112.98 84.57,111.25 v1(84.93,110.9)
  BOTTOM w0.508: U16.AK14 v1(71.24,51.06)
DD_C5P: length 145.2
  LY6-SIG w0.107: v1(84.01,110.9) 84.29,110.61 84.29,109.55 81.65,106.9 81.65,97.99 81.3,97.64 80.69,97.64 80.44,97.89 80.44,103.84 79.9,104.37 79.11,104.37 78.6,103.85 78.6,70.36 78.3,70.06 77.77,70.06 77.39,70.43 77.39,95.89 76.92,96.36 76.18,96.36 75.66,95.83 75.66,67.89 77.13,66.42 77.13,64.59 76.37,63.83 72.81,63.83 71.52,62.54 71.52,56.13 73.42,54.22 73.42,52.35 72.56,51.48 72.31,51.48 72.16,51.63 72.16,51.98 v1(72.51,52.33)
  BOTTOM w0.127: J3.41 84.86,115.32 84.98,115.2 84.98,113.74 84.32,113.08 84.32,111.21 v1(84.01,110.9)
  BOTTOM w0.508: U16.AL15 v1(72.51,52.33)
DD_C6N: length 147.5
  LY6-SIG w0.107: v1(87.93,112.77) 87.62,112.46 87.62,111.93 88.16,111.4 88.16,109.32 86.59,107.74 86.59,96.34 86.07,95.83 84.98,95.83 84.39,96.42 84.39,106.65 84.14,106.9 83.66,106.9 83.38,106.63 83.38,69.96 82.95,69.52 82.16,69.52 81.73,69.95 81.73,93.62 81.51,93.85 80.82,93.85 80.51,93.54 80.51,68.1 79.52,67.11 79.52,56.6 76.43,53.5 76.43,51.89 76.95,51.37 78.29,51.37 78.4,51.48 78.4,52.13 78.2,52.33 v1(77.59,52.33)
  BOTTOM w0.127: J3.46 87.36,115.32 87.23,115.2 87.23,114.3 87.6,113.94 87.6,113.1 v1(87.93,112.77)
  BOTTOM w0.508: U16.AL17 v1(77.59,52.33)
DD_C6P: length 146.9
  LY6-SIG w0.107: v1(78.86,51.06) 76.82,51.06 76.12,51.76 76.12,53.62 79.21,56.72 79.21,67.24 80.2,68.22 80.2,93.67 80.69,94.16 81.63,94.16 82.04,93.75 82.04,70.08 82.29,69.83 82.82,69.83 83.07,70.08 83.07,106.76 83.53,107.21 84.27,107.21 84.7,106.78 84.7,96.55 85.11,96.14 85.95,96.14 86.28,96.47 86.28,107.87 87.85,109.45 87.85,111.27 87.31,111.81 87.31,112.46 v1(87.01,112.77)
  BOTTOM w0.127: v1(87.01,112.77) 87.34,113.1 87.34,113.84 86.98,114.2 86.98,115.2 86.86,115.32 J3.45
  BOTTOM w0.508: U16.AK18 v1(78.86,51.06)
DD_C7N: length 148.5
  LY6-SIG w0.107: v1(89.58,113.36) 89.23,113.01 89.23,105.28 92.96,101.54 92.96,97.07 94.07,95.96 94.07,76.35 92.86,75.13 90.57,75.13 89.55,76.15 89.55,87.16 89.29,87.43 88.45,87.43 88.18,87.16 88.18,70.97 87.69,70.48 86.64,70.48 86.17,70.95 86.17,93.81 85.81,94.18 85.27,94.18 84.93,93.85 84.93,69.22 82.95,67.23 82.95,63.58 81.56,62.19 81.56,53.32 81.35,53.1 81.35,52.88 81.9,52.33 v1(82.67,52.33)
  BOTTOM w0.127: J3.50 89.36,115.22 89.25,115.11 89.25,113.69 v1(89.58,113.36)
  BOTTOM w0.508: U16.AL21 v1(82.67,52.33)
DD_C7P: length 147.9
  LY6-SIG w0.107: v1(88.66,113.36) 88.92,113.1 88.92,105.15 92.65,101.41 92.65,96.94 93.76,95.83 93.76,76.47 92.73,75.44 90.7,75.44 89.86,76.28 89.86,87.29 89.41,87.74 88.32,87.74 87.87,87.29 87.87,71.1 87.56,70.79 86.76,70.79 86.48,71.07 86.48,93.94 85.94,94.49 85.14,94.49 84.62,93.97 84.62,69.35 82.64,67.36 82.64,63.7 81.25,62.32 81.25,53.44 v1(80.13,52.33)
  BOTTOM w0.127: v1(88.66,113.36) 88.99,113.69 88.99,115.14 88.86,115.27 J3.49
  BOTTOM w0.508: U16.AL19 v1(80.13,52.33)
DD_D0N: length 152.6
  LY6-SIG w0.107: v1(83.94,51.06) 83.94,56.45 86.09,58.6 86.09,65.81 89.56,69.27 104.89,69.27 106.09,68.07 106.09,57.81 106.98,56.93 107.81,56.93 108.58,57.69 108.58,95.57 109.37,96.37 112.13,96.37 112.87,95.63 112.87,88.16 113.48,87.55 114.75,87.55 115.13,87.93 115.13,97.68 114.39,98.42 111.63,98.42 109.62,100.43 109.62,106.34 108.17,107.79 108.17,109.53 111,112.36 112.26,112.36 112.56,112.65 112.56,113.31 112.18,113.69 112.18,115.52 112.97,116.31 116.38,116.31 117.12,115.57 117.12,113.88 117.06,113.82 117.06,112.85 v1(117.36,112.55)
  BOTTOM w0.127: v1(117.36,112.55) 117.05,112.86 117.05,115.2 117.18,115.32 J4.18
  BOTTOM w0.508: U16.AK22 v1(83.94,51.06)
DD_D0P: length 152.1
  LY6-SIG w0.107: v1(85.21,52.33) 85.21,51.92 85.13,51.84 84.55,51.84 84.25,52.13 84.25,56.32 86.4,58.47 86.4,65.68 89.69,68.96 104.77,68.96 105.78,67.94 105.78,57.68 106.85,56.62 107.94,56.62 108.89,57.56 108.89,95.45 109.5,96.06 112,96.06 112.56,95.5 112.56,88.03 113.35,87.24 114.88,87.24 115.44,87.8 115.44,97.81 114.52,98.73 111.76,98.73 109.93,100.56 109.93,106.47 108.48,107.92 108.48,109.4 111.12,112.05 112.39,112.05 112.87,112.52 112.87,113.44 112.49,113.82 112.49,115.39 113.1,116 116.25,116 116.81,115.44 116.81,114.01 116.75,113.95 116.75,112.85 v1(116.45,112.55)
  BOTTOM w0.127: v1(116.45,112.55) 116.8,112.9 116.8,115.2 116.68,115.32 J4.17
  BOTTOM w0.508: U16.AL23 v1(85.21,52.33)
DD_D1N: length 150.4
  LY6-SIG w0.107: v1(119.39,113.31) 119.08,113 119.08,112.67 117.85,111.44 117.73,111.44 116.3,110 116.3,102.59 117.83,101.07 117.83,68.93 117.13,68.22 113.75,68.22 113.05,68.93 113.05,85.14 112.62,85.57 111.55,85.57 111.05,85.06 111.05,57.3 108.48,54.73 105.13,54.73 104.18,55.68 104.18,63.78 102.25,65.71 91.41,65.71 90.06,64.36 90.06,58.22 88.11,56.26 88.11,53.54 88.71,52.94 88.71,51.91 88.01,51.21 87.22,51.21 87.07,51.06 v1(86.48,51.06)
  BOTTOM w0.127: J4.22 119.18,115.32 119.05,115.2 119.05,113.64 v1(119.39,113.31)
  BOTTOM w0.508: U16.AK24 v1(86.48,51.06)
DD_D1P: length 150
  LY6-SIG w0.107: v1(118.47,113.31) 118.77,113 118.77,112.8 117.72,111.75 117.61,111.75 115.99,110.13 115.99,102.46 117.52,100.94 117.52,69.05 117,68.53 113.88,68.53 113.36,69.05 113.36,85.27 112.75,85.88 111.42,85.88 110.74,85.19 110.74,57.43 108.35,55.04 105.26,55.04 104.49,55.8 104.49,63.91 102.38,66.02 91.28,66.02 89.75,64.49 89.75,58.34 87.8,56.39 87.8,53.42 88.4,52.81 88.4,52.04 87.88,51.52 87.45,51.52 87.29,51.68 87.29,51.86 v1(87.75,52.33)
  BOTTOM w0.127: J4.21 118.68,115.32 118.8,115.2 118.8,113.64 v1(118.47,113.31)
  BOTTOM w0.508: U16.AL25 v1(87.75,52.33)
DD_D2N: length 147.9
  LY6-SIG w0.107: v1(121.45,112.32) 121.15,112.01 121.15,111.22 118.74,108.81 118.74,107.14 119.12,106.76 121.96,106.76 123.92,104.79 123.92,81.61 123.44,81.13 122.7,81.13 122.17,81.66 122.17,103.6 121.8,103.96 120.67,103.96 120.11,103.4 120.11,64.54 109.09,53.51 106.5,53.51 105.05,52.07 96.13,52.07 92.68,55.52 90.85,55.52 89.63,54.31 89.63,51.77 89.79,51.61 90.16,51.61 90.29,51.75 v1(90.29,52.33)
  BOTTOM w0.127: J4.26 121.17,115.32 121.05,115.2 121.05,112.72 v1(121.45,112.32)
  BOTTOM w0.508: U16.AL27 v1(90.29,52.33)
DD_D2P: length 147.3
  LY6-SIG w0.107: v1(89.02,51.06) 89.32,51.36 89.32,54.44 90.72,55.83 92.8,55.83 96.26,52.38 104.92,52.38 106.37,53.82 108.96,53.82 119.8,64.67 119.8,103.52 120.55,104.27 121.93,104.27 122.48,103.72 122.48,81.79 122.83,81.44 123.31,81.44 123.61,81.74 123.61,104.67 121.83,106.45 118.99,106.45 118.43,107.01 118.43,108.94 120.84,111.35 120.84,112.01 v1(120.53,112.32)
  BOTTOM w0.127: J4.25 120.68,115.32 120.8,115.2 120.8,113.03 120.53,112.77 v1(120.53,112.32)
  BOTTOM w0.508: U16.AK26 v1(89.02,51.06)
DD_D3N: length 141.5
  LY6-SIG w0.107: v1(123.38,113.31) 123.08,113.61 123.08,114.88 127.7,119.51 135.6,119.51 144.51,110.6 144.51,74.07 109.49,39.04 99.61,39.04 96.99,36.42 95.01,36.42 94.56,36.88 93.74,36.88 93.08,36.22 93.08,35.33 93.62,34.8 94.41,34.8 94.99,35.38 95.18,35.38 95.37,35.19 v1(95.37,34.55)
  BOTTOM w0.127: v1(123.38,113.31) 123.05,113.64 123.05,115.2 123.17,115.32 J4.30
  BOTTOM w0.508: U16.U31 v1(95.37,34.55)
DD_D3P: length 140.9
  LY6-SIG w0.107: v1(94.1,35.82) 94.45,35.48 94.45,35.27 94.28,35.11 93.74,35.11 93.39,35.46 93.39,36.09 93.87,36.57 94.43,36.57 94.88,36.11 97.12,36.11 99.74,38.73 109.62,38.73 144.82,73.94 144.82,110.72 135.73,119.82 127.57,119.82 122.77,115.01 122.77,113.61 v1(122.46,113.31)
  BOTTOM w0.127: v1(122.46,113.31) 122.8,113.64 122.8,115.2 122.67,115.32 J4.29
  BOTTOM w0.508: U16.V30 v1(94.1,35.82)
DD_D4N: length 147.7
  LY6-SIG w0.107: v1(95.37,44.71) 94.99,45.1 94.99,45.37 97.8,48.18 105.33,48.18 108.04,50.9 110.33,50.9 126.64,67.21 126.64,90.78 126.89,91.03 127.68,91.03 127.88,90.83 127.88,69.64 128.4,69.11 129.09,69.11 129.61,69.64 129.61,87.13 131.21,88.72 131.21,108.13 130.8,108.53 130.19,108.53 129.88,108.22 129.88,105.77 129.72,105.61 129.29,105.61 129.18,105.72 129.18,107.72 128.74,108.16 127.31,108.16 127.07,108.4 127.07,111.84 v1(127.4,112.17)
  BOTTOM w0.127: J4.38 127.17,115.32 127.05,115.2 127.05,112.51 v1(127.4,112.17)
  BOTTOM w0.508: U16.AE31 v1(95.37,44.71)
DD_D4P: length 147.1
  LY6-SIG w0.107: v1(126.48,112.17) 126.76,111.88 126.76,108.27 127.19,107.85 128.61,107.85 128.87,107.59 128.87,105.59 129.16,105.3 129.85,105.3 130.19,105.64 130.19,108.1 130.32,108.22 130.67,108.22 130.9,108 130.9,88.85 129.3,87.25 129.3,69.76 128.96,69.42 128.53,69.42 128.19,69.76 128.19,90.96 127.81,91.34 126.76,91.34 126.33,90.91 126.33,67.33 110.2,51.21 107.92,51.21 105.2,48.49 97.67,48.49 95.16,45.98 v1(94.1,45.98)
  BOTTOM w0.127: J4.37 126.67,115.32 126.8,115.2 126.8,112.48 v1(126.48,112.17)
  BOTTOM w0.508: U16.AF30 v1(94.1,45.98)
DD_D5N: length 145.5
  LY6-SIG w0.107: v1(94.1,38.36) 93.74,38 93.74,37.69 93.97,37.46 94.76,37.46 95.07,37.77 95.07,38.03 97.86,40.82 105.88,40.82 107.89,42.83 111.5,42.83 139.53,70.87 139.53,78.39 140.08,78.94 141.1,78.94 141.65,78.39 141.65,74.45 141.95,74.15 142.81,74.15 143.12,74.45 143.12,110.34 134.99,118.46 129.92,118.46 128.62,117.16 128.62,113.16 128.41,112.95 128.41,110.84 128.42,110.83 128.42,110.59 v1(128.72,110.29)
  BOTTOM w0.127: J4.42 129.17,115.32 129.05,115.2 129.05,113.64 128.39,112.98 128.39,110.62 v1(128.72,110.29)
  BOTTOM w0.508: U16.Y30 v1(94.1,38.36)
DD_D5P: length 144.8
  LY6-SIG w0.107: v1(127.8,110.29) 128.11,110.59 128.11,110.71 128.1,110.71 128.1,113.08 128.31,113.28 128.31,117.29 129.79,118.77 135.11,118.77 143.43,110.46 143.43,74.32 142.94,73.84 141.82,73.84 141.34,74.32 141.34,78.26 140.97,78.63 140.21,78.63 139.84,78.26 139.84,70.74 111.62,42.52 108.02,42.52 106.01,40.51 97.98,40.51 95.37,37.9 v1(95.37,37.09)
  BOTTOM w0.127: J4.41 128.67,115.32 128.8,115.2 128.8,113.74 128.13,113.08 128.13,110.62 v1(127.8,110.29)
  BOTTOM w0.508: U16.W31 v1(95.37,37.09)
DD_D6N: length 150
  LY6-SIG w0.107: v1(95.37,39.63) 95.37,40.02 95.22,40.18 94.61,40.18 94.15,39.72 93.69,39.72 93.11,40.31 93.11,41.43 93.62,41.93 94.53,41.93 95.03,41.43 96.84,41.43 98.31,42.9 106.11,42.9 107.91,44.71 111.22,44.71 134.23,67.72 134.23,82.28 134.65,82.71 135.97,82.71 136.39,82.28 136.39,71.16 136.76,70.79 137.42,70.79 137.79,71.16 137.79,81.69 141.72,85.63 141.72,110.21 134.62,117.32 131.84,117.32 131.44,116.91 131.44,113.07 v1(131.74,112.77)
  BOTTOM w0.127: v1(131.74,112.77) 131.41,113.1 131.41,113.94 131.05,114.3 131.05,115.2 131.17,115.32 J4.46
  BOTTOM w0.508: U16.AA31 v1(95.37,39.63)
DD_D6P: length 149.4
  LY6-SIG w0.107: v1(130.82,112.77) 131.13,113.07 131.13,117.04 131.72,117.63 134.75,117.63 142.03,110.34 142.03,85.5 138.1,81.56 138.1,71.03 137.55,70.48 136.63,70.48 136.08,71.03 136.08,82.16 135.84,82.4 134.78,82.4 134.54,82.16 134.54,67.59 111.35,44.4 108.04,44.4 106.24,42.59 98.44,42.59 96.97,41.12 94.9,41.12 94.4,41.62 93.74,41.62 93.42,41.3 93.42,40.44 93.82,40.03 94.02,40.03 94.1,40.12 v1(94.1,40.9)
  BOTTOM w0.127: v1(130.82,112.77) 131.16,113.1 131.16,113.84 130.8,114.2 130.8,115.2 130.67,115.32 J4.45
  BOTTOM w0.508: U16.AB30 v1(94.1,40.9)
DD_D7N: length 147.5
  LY6-SIG w0.107: v1(95.37,42.17) 95.66,42.45 95.66,42.53 95.76,42.64 96.96,42.64 98.85,44.53 106.21,44.53 108.02,46.33 111.19,46.33 133.22,68.36 133.22,82.96 136.19,85.93 136.19,103.68 136.75,104.24 137.92,104.24 138.31,103.85 138.31,86.32 138.92,85.72 140.08,85.72 140.68,86.32 140.68,110.26 139.48,111.45 133.64,111.45 132.79,112.31 132.79,112.97 133.2,113.38 v1(133.65,113.38)
  BOTTOM w0.127: v1(133.65,113.38) 133.34,113.69 132.99,113.69 132.73,113.95 132.73,114.52 133.17,114.97 J4.50
  BOTTOM w0.508: U16.AC31 v1(95.37,42.17)
DD_D7P: length 146.9
  LY6-SIG w0.107: v1(132.48,113.36) 132.48,112.18 133.51,111.14 139.35,111.14 140.37,110.13 140.37,86.45 139.95,86.03 139.04,86.03 138.62,86.45 138.62,103.98 138.05,104.55 136.62,104.55 135.88,103.81 135.88,86.06 132.91,83.09 132.91,68.48 111.06,46.64 107.89,46.64 106.09,44.83 98.72,44.83 96.84,42.95 94.59,42.95 v1(94.1,43.44)
  BOTTOM w0.127: J4.49 132.67,114.83 132.48,114.63 v1(132.48,113.36)
  BOTTOM w0.508: U16.AD30 v1(94.1,43.44)
DMD_EN_ARSTZ: length 155.5
  TOP w0.203: J1.9 85.86,115.08 85.64,114.86 85.64,113.08 v1(85.87,112.85) ; U23.2 v1(110.68,16.28)
  LY6-SIG w0.119: v1(110.68,16.28) 109.11,14.71 107.3,14.71 106.75,14.16 101.77,14.16 101.26,14.67 93.53,14.67 93.26,14.95 92.46,14.95 92.17,14.66 91.25,14.66 88.28,17.63 88.28,20.6 90.82,23.14 90.82,40.03 81.88,48.97 81.88,50.37 83.35,51.84 83.35,52.73 82.59,53.49 82.59,57.99 84.32,59.71 84.32,65.33 98.59,79.6 98.59,113.21 94.15,117.65 88.69,117.65 87.37,116.33 87.37,114.02 86.52,113.17 86.19,113.17 v1(85.87,112.85)
DMD_EN_ARSTZ_BUF: length 83.4
  TOP w0.203: U23.4 106.36,17.23 106.16,17.02 106.16,16.62 v1(105.8,16.27)
  LY2-SIG w0.145: v1(90.29,19.31) 90.29,20.69 89.37,21.61 89.37,22.27 91.25,24.15 91.25,24.97 88.15,28.07 88.15,42.97 86.42,44.71 v1(85.21,44.71) 85.2,44.69 85.2,43.14 83.86,41.81 62.81,41.81 59.36,38.36 v1(58.54,38.36)
  LY6-SIG w0.119: v1(105.8,16.27) 105.03,16.27 104.66,15.9 95.14,15.9 91.73,19.31 v1(90.29,19.31)
  BOTTOM w0.203: R44.2 106.05,16.52 v1(105.8,16.27)
  BOTTOM w0.508: U16.Y4 v1(58.54,38.36) ; U16.AE23 v1(85.21,44.71) ; U16.E27 v1(90.29,19.31)
DMD_PWR_EN: length 167.8
  TOP w0.203: U6.3 v1(11.9,89.31) ; v1(67.07,97.13) 67.78,97.13 67.97,97.31 U25.1 ; R10.2 v1(51.32,117.8) 50.85,117.8 50.83,117.78 50.56,117.78 50.05,118.29 J6.2 ; v1(90.99,100.48) 91.05,100.42 U12.1 92.1,99.92 92.08,99.9 R43.2 ; v1(87.32,88.87) 88.1,88.87 88.29,89.06 U24.1 ; J1.7 86.86,115.24 86.91,115.19 86.91,113.44 86.45,112.98 86.45,112.47 87.8,111.12 87.8,108.96 v1(88.21,108.56)
  LY2-SIG w0.145: v1(88.21,108.56) 82.31,102.67 82.31,101.24 79.06,97.99 67.89,97.99 67.07,97.18 v1(67.07,97.13) 65.65,98.55 65.65,101.27 67.76,103.38 67.76,116.46 67.25,116.97 52.16,116.97 v1(51.32,117.8) 50.87,117.8 50.82,117.85 30.09,117.85 16.4,104.16 16.4,92.71 13,89.31 v1(11.9,89.31)
  LY4-SIG w0.165: v1(88.21,108.56) 90.99,105.78 v1(90.99,100.48)
  LY6-SIG w0.119: v1(87.32,88.87) 87.32,90.55 88.41,91.64 88.41,97.9 v1(90.99,100.48)
  BOTTOM w0.203: R60.1 87.37,88.82 v1(87.32,88.87) ; v1(67.07,97.13) 67.05,97.1 R63.1
DMD_RESERVED: length 133.3
  TOP w0.203: v1(116.92,24.22) 116.92,23.35 116.58,23.01 U22.2 ; J2.11 128.67,115.13 128.77,115.04 128.77,113.74 128.64,113.61 128.64,111.69 129.01,111.33 v1(129.48,111.33)
  LY2-SIG w0.145: v1(129.48,111.33) 128.6,111.33 128.36,111.57 128.36,112.04 126.43,113.97 114.62,113.97 112.75,112.09 111.93,112.09 111.42,111.58 111.42,110.41 114.77,107.06 118.66,107.06 132.1,93.62 132.1,39.39 v1(116.92,24.22)
DMD_RSVD_BUF: length 5.9
  TOP w0.203: v1(110,22.99) 112.23,22.99 112.46,23.21 112.46,23.96 U22.4
  BOTTOM w0.203: R45.2 109.26,22.25 v1(110,22.99)
DMD_TP0: length 32.1
  TOP w0.203: J10.1 41.8,60.6 42.18,60.22 v1(43.45,60.22)
  LY2-SIG w0.145: v1(63.62,48.52) 63.62,47.38 62.75,46.51 61.74,46.51 56.15,52.09 52.47,52.09 49.42,55.14 48.53,55.14 v1(43.45,60.22)
  BOTTOM w0.508: U16.AH8 v1(63.62,48.52)
DMD_TP1: length 27.4
  TOP w0.203: J10.2 46.88,62.76 v1(46.37,62.25)
  LY2-SIG w0.145: v1(62.35,47.25) 62.35,48.81 57.67,53.49 54.75,53.49 50.82,57.43 50.82,57.81 v1(46.37,62.25)
  BOTTOM w0.508: U16.AG7 v1(62.35,47.25)
DMD_TP2: length 37.5
  TOP w0.203: J10.3 41.8,64.79 v1(41.55,64.54)
  LY2-SIG w0.145: v1(64.89,47.25) 64.89,48.68 59.71,53.87 59.71,57.3 53.48,63.52 42.56,63.52 v1(41.55,64.54)
  BOTTOM w0.508: U16.AG9 v1(64.89,47.25)
DMUX_LATCHED: length 29.5
  TOP w0.203: U18.5 107.82,92.97 107.46,92.61 v1(106.44,92.61)
  LY6-SIG w0.119: v1(106.44,92.61) 105.68,93.37 105.68,94.26 106.7,95.27 106.7,110.39 110.13,113.82 v1(111.27,113.82)
  BOTTOM w0.203: v1(111.27,113.82) 111.68,114.22 J4.7
DMUX_OUT: length 146.3
  TOP w0.203: J8.2 137.68,17.01 137.43,16.75 v1(137.43,16.28) ; U18.1 104.55,95.39 v1(103.9,96.04) 103.9,96.02 R57.2
  LY2-SIG w0.145: v1(137.43,16.28) 136.29,15.14 115.71,15.14 113.43,17.42 106.06,17.42 105.43,18.06 95.39,18.06 94.14,19.31 v1(92.83,19.31)
  LY4-SIG w0.165: v1(92.83,19.31) 93.13,19.61 94.29,19.61 94.77,20.09 94.77,28.66 94.56,28.87 94.56,29.68 95.09,30.22 95.79,30.22 96.13,30.57 96.55,30.57 97.28,31.29 97.28,34.29 100.67,37.68 103.55,37.68 104.9,39.02 108.59,39.02 110.39,40.83 110.39,45.75 109.47,46.67 109.47,85.96 108.24,87.19 108.24,94.15 107.32,95.07 105.55,95.07 104.59,96.04 v1(103.9,96.04)
  BOTTOM w0.508: U16.E29 v1(92.83,19.31)
